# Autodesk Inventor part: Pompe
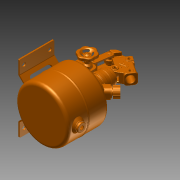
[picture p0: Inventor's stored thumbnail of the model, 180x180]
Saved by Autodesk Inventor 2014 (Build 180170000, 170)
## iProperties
Created: 2015-07
Part Number: Pompe
Material: Générique
Document SubType Name: Modeling
Designer: OL
Density: 1 g/cm^3
Appearance: Par défaut
Norme de conversion: STEP AP203
Nom du fichier: P16S1+RP2.STEP
Préprocesseur: SolidWorks 2007
Postprocesseur: Build: 138, Release: 2013 RTM - Date: Thu 03/01/2012
Unités envoyées: millimètre
Incertitude: 1e-05
Author: OL
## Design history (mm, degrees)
node "P16S1+RP21"
feature "Composite1"
body "Srf1"
